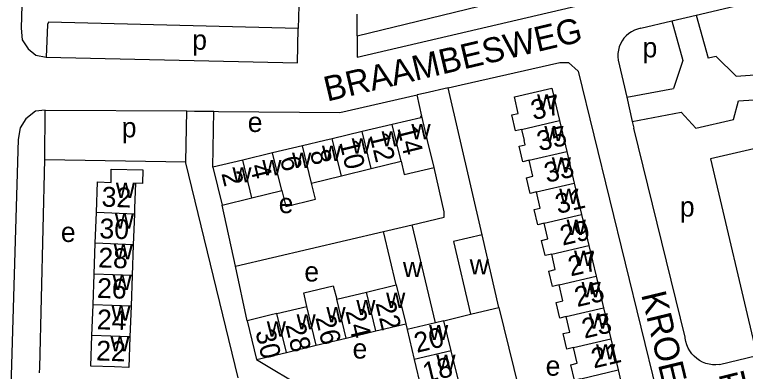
# Model space of a CAD drawing. Extents: x 161936 to 163647, y 386450 to 388633.
# Drawn here: x 162905.7 to 163052.8, y 387703.5 to 387775.4 of the extents above; entities that cross this region are included whole.
import ezdxf

# ---------------------------------------------------------------- set-up
doc = ezdxf.new("R2010")
doc.units = 0
for name, color, linetype in [('BLT_Basislijn', 7, 'Continuous'), ('BLT_Bebouwing', 7, 'Continuous'), ('BLT_Centroide', 7, 'Continuous'), ('BLT_Huisnummer', 7, 'Continuous'), ('BLT_Huisnummer_ tussenligend', 7, 'Continuous'), ('BLT_Onderverdeling_panden', 7, 'Continuous'), ('BLT_Straatnaam', 7, 'Continuous')]:
    doc.layers.add(name, color=color, linetype=linetype)

msp = doc.modelspace()

# ---------------------------------------------------------------- linework, layer by layer
at = {"layer": 'BLT_Basislijn'}
for p, q in [((163042.83, 387775.25), (163135.83, 387797.38)), ((162974.6, 387771.09), (163056.45, 387791.04)), ((162962.89, 387777.14), (162962.72, 387772.56)), ((162974.6, 387771.09), (162974.61, 387775.46)), ((163037.96, 387774.1), (163042.83, 387775.25)), ((163042.83, 387775.25), (163045.25, 387766.59)), ((163031.7, 387772.61), (163037.96, 387774.1)), ((163037.96, 387774.1), (163040.19, 387766.11)), ((163027.15, 387766.18), (163028.87, 387758.74)), ((163040.19, 387766.11), (163038.28, 387760.49)), ((162999.76, 387731.03), (162992.94, 387760.63)), ((163028.87, 387758.74), (163038.28, 387760.49)), ((162987.66, 387754.89), (162986.68, 387759.19)), ((163028.87, 387758.74), (163029.99, 387753.86)), ((162911.78, 387746.16), (162911.85, 387756.12)), ((162911.85, 387756.12), (162940.32, 387755.95)), ((162940.13, 387745.73), (162940.32, 387755.95)), ((162945.57, 387744.63), (162945.79, 387755.88)), ((163029.99, 387753.86), (163039.8, 387755.68)), ((163029.99, 387753.86), (163030.3, 387752.52)), ((163040.64, 387710.4), (163030.3, 387752.52)), ((162911.78, 387746.16), (162940.13, 387745.73)), ((162950.1, 387724.67), (162947.44, 387737.01)), ((162950.1, 387724.67), (162979.91, 387731.65)), ((162952.47, 387713.71), (162950.1, 387724.67)), ((163003.16, 387716.38), (163011.93, 387680.2)), ((162992.08, 387713.71), (162997.43, 387715.04)), ((162954.35, 387705.88), (162966.71, 387698.54)), ((163047.53, 387704.91), (163055.08, 387706.71))]:
    msp.add_line(p, q, dxfattribs=at)
for points in [[(162915.89, 387918.97), (162915.01, 387918.97), (162913.37, 387918.42), (162912.22, 387917.52), (162911.2, 387915.93), (162911.09, 387914.53), (162906.98, 387772.65), (162907.22, 387770.28), (162908.42, 387768.43), (162909.94, 387767.19), (162912.05, 387766.8)], [(162974.6, 387771.09), (162974.59, 387766.81), (163051.97, 387784.91), (163053.26, 387785.27), (163056.22, 387788.49), (163056.45, 387791.04)], [(162962.72, 387772.56), (162912.49, 387773.8), (162912.26, 387773.37), (162912.05, 387766.8)], [(162912.05, 387766.8), (162962.59, 387765.65), (162962.72, 387772.56)], [(163031.7, 387772.61), (163031.05, 387772.45), (163030.42, 387772.22), (163029.83, 387771.91), (163029.27, 387771.53), (163028.77, 387771.09), (163028.32, 387770.6), (163027.93, 387770.05), (163027.61, 387769.46), (163027.36, 387768.84), (163027.19, 387768.19), (163027.1, 387767.53), (163027.09, 387766.86), (163027.15, 387766.18)], [(163050.87, 387762.96), (163046.85, 387766.9), (163045.25, 387766.59)], [(162992.94, 387760.63), (162995.56, 387761.23), (163015.41, 387765.73), (163017.12, 387765.68), (163019.13, 387763.98), (163038.02, 387686.62), (163038.08, 387686.35)], [(163050.87, 387762.96), (163060.21, 387763.61), (163071.43, 387754.4)], [(162992.94, 387760.63), (162988.31, 387759.56), (162986.68, 387759.19)], [(162945.79, 387755.88), (162946.68, 387755.87), (162971.15, 387755.62), (162986.68, 387759.19)], [(163039.8, 387755.68), (163042.78, 387752.51), (163050.39, 387754.23), (163051.4, 387757.99)], [(163051.4, 387757.99), (163058.57, 387758.49), (163067.14, 387751.45)], [(162911.85, 387756.12), (162909.89, 387755.9), (162907.95, 387754.34), (162906.79, 387752.55), (162906.35, 387750.21), (162903.24, 387643.73), (162900.86, 387641.66), (162900.54, 387640.21), (162900.7, 387625.17), (162903.24, 387620), (162914.45, 387609.13)], [(162940.32, 387755.95), (162941.88, 387755.94), (162945.79, 387755.88)], [(163055.32, 387748.56), (163045.72, 387746.32), (163055.08, 387706.71)], [(162910.69, 387703.24), (162910.72, 387704.27), (162911.78, 387746.16)], [(162950.67, 387702.21), (162940.12, 387745.51), (162940.13, 387745.73)], [(162985.66, 387733.03), (162992.13, 387734.59), (162992.13, 387735.62), (162990.1, 387744.58)], [(163047.53, 387704.91), (163046.84, 387704.85), (163046.15, 387704.86), (163045.46, 387704.96), (163044.79, 387705.13), (163044.14, 387705.38), (163043.53, 387705.7), (163042.96, 387706.09), (163042.43, 387706.55), (163041.97, 387707.06), (163041.56, 387707.62), (163041.22, 387708.22), (163040.96, 387708.86), (163040.77, 387709.53), (163040.65, 387710.21), (163040.64, 387710.4)]]:
    msp.add_lwpolyline(points, dxfattribs=at)
at = {"layer": 'BLT_Bebouwing'}
for p, q in [((163013.79, 387760.55), (163015.32, 387754.04)), ((162981.63, 387753.22), (162975.62, 387751.79)), ((163015.32, 387754.04), (163016.79, 387747.8)), ((162975.62, 387751.79), (162969.61, 387750.36)), ((163007.72, 387752.25), (163008.25, 387750)), ((162963.6, 387748.93), (162957.59, 387747.49)), ((162957.59, 387747.49), (162951.58, 387746.06)), ((163016.79, 387747.8), (163018.29, 387741.42)), ((162951.58, 387746.06), (162945.57, 387744.63)), ((162977.44, 387744.36), (162983.44, 387745.83)), ((162945.57, 387744.63), (162947.44, 387737.01)), ((162971.44, 387742.89), (162977.44, 387744.36)), ((162965.44, 387741.42), (162971.44, 387742.89)), ((163018.29, 387741.42), (163019.78, 387735.1)), ((162953.44, 387738.48), (162959.44, 387739.95)), ((162947.44, 387737.01), (162953.44, 387738.48)), ((162921.89, 387729.3), (162922.12, 387735.48)), ((162929.78, 387735.2), (162929.56, 387729.02)), ((163019.78, 387735.1), (163021.24, 387728.89)), ((162990.4, 387713.31), (162985.66, 387733.03)), ((162982.49, 387720.91), (162979.91, 387731.65)), ((163003.16, 387716.38), (162999.76, 387731.03)), ((162921.67, 387723.12), (162921.89, 387729.3)), ((162929.56, 387729.02), (162929.33, 387722.85)), ((163021.24, 387728.89), (163022.71, 387722.66)), ((162921.45, 387716.94), (162921.67, 387723.12)), ((162929.33, 387722.85), (162929.11, 387716.67)), ((163022.71, 387722.66), (163024.2, 387716.31)), ((162976.5, 387719.48), (162982.49, 387720.91)), ((162970.49, 387718.03), (162976.5, 387719.48)), ((162921.22, 387710.77), (162921.45, 387716.94)), ((162929.11, 387716.67), (162928.88, 387710.49)), ((162958.48, 387715.15), (162964.49, 387716.59)), ((163000, 387715.64), (163003.16, 387716.38)), ((163024.2, 387716.31), (163025.68, 387710.05)), ((162997.43, 387715.04), (163000, 387715.64)), ((162952.47, 387713.71), (162954.35, 387705.88)), ((162978.38, 387711.65), (162984.38, 387713.1)), ((162984.38, 387713.1), (162984.65, 387711.98)), ((162992.08, 387713.71), (162990.4, 387713.31)), ((162993.53, 387707.68), (162992.08, 387713.71)), ((162972.37, 387710.21), (162978.38, 387711.65)), ((162984.65, 387711.98), (162986.11, 387705.9)), ((162966.36, 387708.77), (162972.37, 387710.21)), ((162960.36, 387707.33), (162966.36, 387708.77)), ((163025.68, 387710.05), (163027.15, 387703.8)), ((162954.35, 387705.88), (162960.36, 387707.33)), ((162994.98, 387701.65), (162993.53, 387707.68)), ((162986.11, 387705.9), (162987.56, 387699.87)), ((163027.15, 387703.8), (163028.63, 387697.51))]:
    msp.add_line(p, q, dxfattribs=at)
for points in [[(163007.72, 387752.25), (163006.47, 387751.96), (163005.72, 387755.16), (163007.04, 387755.47), (163006.26, 387758.78), (163013.79, 387760.55)], [(162987.66, 387754.89), (162987.36, 387754.82), (162987.42, 387754.6), (162981.63, 387753.22)], [(162990.1, 387744.58), (162988.8, 387750), (162987.66, 387754.89)], [(162969.61, 387750.36), (162968.11, 387750), (162963.6, 387748.93)], [(163009.22, 387746.02), (163007.97, 387745.73), (163007.24, 387748.84), (163008.45, 387749.12), (163008.25, 387750)], [(162983.44, 387745.83), (162984.1, 387743.15), (162990.1, 387744.58)], [(163010.71, 387739.64), (163009.45, 387739.34), (163008.7, 387742.52), (163009.98, 387742.82), (163009.22, 387746.02)], [(162922.12, 387735.48), (162922.34, 387741.66), (162925.08, 387741.56), (162925.13, 387744.23), (162931.48, 387744.11), (162931.38, 387741.33), (162930, 387741.38), (162929.82, 387736.38), (162929.78, 387735.2)], [(162959.44, 387739.95), (162960.29, 387736.71), (162966.25, 387738.16), (162965.44, 387741.42)], [(163012.25, 387733.33), (163010.97, 387733.03), (163010.25, 387736.11), (163011.47, 387736.39), (163010.71, 387739.64)], [(162979.91, 387731.65), (162980.8, 387731.87), (162985.66, 387733.03)], [(163013.77, 387727.13), (163012.43, 387726.82), (163011.71, 387729.89), (163012.99, 387730.19), (163012.25, 387733.33)], [(162999.76, 387731.03), (162994.02, 387729.69), (162997.43, 387715.04)], [(163015.25, 387720.91), (163013.92, 387720.59), (163013.19, 387723.69), (163014.5, 387724), (163013.77, 387727.13)], [(162964.49, 387716.59), (162963.86, 387719.3), (162969.81, 387720.73), (162970.49, 387718.03)], [(163016.66, 387714.54), (163015.38, 387714.24), (163014.64, 387717.39), (163016, 387717.71), (163015.25, 387720.91)], [(162958.48, 387715.15), (162957.33, 387714.87), (162952.47, 387713.71)], [(163018.16, 387708.29), (163016.81, 387707.97), (163016.06, 387711.11), (163017.4, 387711.43), (163016.66, 387714.54)], [(162928.88, 387710.49), (162928.66, 387704.31), (162925.75, 387704.41), (162921, 387704.59), (162921.22, 387710.77)], [(163019.62, 387702.03), (163018.33, 387701.73), (163017.6, 387704.84), (163018.9, 387705.14), (163018.16, 387708.29)]]:
    msp.add_lwpolyline(points, dxfattribs=at)
at = {"layer": 'BLT_Onderverdeling_panden'}
for p, q in [((162983.44, 387745.83), (162981.63, 387753.22)), ((163007.72, 387752.25), (163015.32, 387754.04)), ((162977.44, 387744.36), (162975.62, 387751.79)), ((162971.44, 387742.89), (162969.61, 387750.36)), ((162965.44, 387741.42), (162963.6, 387748.93)), ((162959.44, 387739.95), (162957.59, 387747.49)), ((163009.22, 387746.02), (163016.79, 387747.8)), ((162953.44, 387738.48), (162951.58, 387746.06)), ((163010.71, 387739.64), (163018.29, 387741.42)), ((162929.78, 387735.2), (162922.12, 387735.48)), ((163012.25, 387733.33), (163019.78, 387735.1)), ((162929.56, 387729.02), (162921.89, 387729.3)), ((163013.77, 387727.13), (163021.24, 387728.89)), ((162929.33, 387722.85), (162921.67, 387723.12)), ((163015.25, 387720.91), (163022.71, 387722.66)), ((162982.49, 387720.91), (162984.38, 387713.1)), ((162978.38, 387711.65), (162976.5, 387719.48)), ((162972.37, 387710.21), (162970.49, 387718.03)), ((162929.11, 387716.67), (162921.45, 387716.94)), ((162966.36, 387708.77), (162964.49, 387716.59)), ((163016.66, 387714.54), (163024.2, 387716.31)), ((162960.36, 387707.33), (162958.48, 387715.15)), ((162990.4, 387713.31), (162984.65, 387711.98)), ((162928.88, 387710.49), (162921.22, 387710.77)), ((163018.16, 387708.29), (163025.68, 387710.05)), ((162993.53, 387707.68), (162986.11, 387705.9)), ((163019.62, 387702.03), (163027.15, 387703.8))]:
    msp.add_line(p, q, dxfattribs=at)

# ---------------------------------------------------------------- texts
at = {"layer": 'BLT_Centroide'}
for s, p in [('p', (162941.42, 387768.28)), ('p', (163032.05, 387766.74)), ('w', (163010.83, 387756.25)), ('e', (162952.59, 387751.72)), ('p', (162927.23, 387750.64)), ('w', (162985.53, 387750.25)), ('w', (163012.29, 387749.88)), ('w', (162979.53, 387748.8)), ('w', (162973.52, 387747.34)), ('w', (162967.52, 387745.91)), ('w', (162961.52, 387744.45)), ('w', (162955.52, 387743)), ('w', (163013.79, 387743.56)), ('w', (162949.5, 387741.55)), ('w', (162926.05, 387738.44)), ('w', (163015.28, 387737.22)), ('e', (162958.82, 387735.38)), ('p', (163039.57, 387734.69)), ('w', (162925.84, 387732.25)), ('w', (163016.78, 387730.97)), ('e', (162914.98, 387729.57)), ('w', (162925.62, 387726.06)), ('w', (163018.27, 387724.75)), ('w', (162983.82, 387722.5)), ('w', (162997.26, 387723.03)), ('e', (162963.98, 387721.61)), ('w', (162925.38, 387719.91)), ('w', (163019.77, 387718.44)), ('w', (162980.44, 387716.28)), ('w', (162974.44, 387714.84)), ('w', (162925.16, 387713.72)), ('w', (162968.42, 387713.39)), ('w', (162962.42, 387711.95)), ('w', (163021.21, 387712.12)), ('w', (162956.42, 387710.52)), ('w', (162989.09, 387709.81)), ('w', (162924.95, 387707.53)), ('e', (162973.69, 387706.09)), ('w', (163022.69, 387705.91)), ('w', (162990.55, 387703.78)), ('e', (163012.55, 387702.64))]:
    msp.add_text(s, height=4, dxfattribs=at).set_placement(p)
at = {"layer": 'BLT_Huisnummer'}
for s, rotation, p in [('37', 13.243, (163010.1, 387754.08)), ('14', 283.7533, (162982.66, 387752.55)), ('10', 283.7543, (162971, 387749.67)), ('6', 283.7535, (162959.04, 387746.4)), ('2', 283.7544, (162947.26, 387743.38)), ('32', 357.9218, (162923.13, 387736.71)), ('31', 13.2418, (163015.02, 387735.19)), ('27', 13.2414, (163017.58, 387722.62)), ('26', 357.9218, (162922.2, 387718.34)), ('22', 283.504, (162978.28, 387717.26)), ('26', 283.504, (162966.19, 387714.35)), ('23', 13.2418, (163020.36, 387710.09)), ('30', 283.5024, (162954.1, 387711.51)), ('20', 13.5027, (162986.62, 387707.23)), ('22', 357.9279, (162922.02, 387705.73))]:
    msp.add_text(s, height=4, rotation=rotation, dxfattribs=at).set_placement(p)
at = {"layer": 'BLT_Huisnummer_ tussenligend'}
for s, rotation, p in [('35', 13.2418, (163011.32, 387747.82)), ('12', 283.7543, (162977.04, 387751.13)), ('8', 283.7535, (162965.08, 387747.69)), ('33', 13.2418, (163012.79, 387741.46)), ('4', 283.7544, (162952.97, 387744.86)), ('30', 357.9218, (162922.69, 387730.33)), ('29', 13.2414, (163015.96, 387728.82)), ('28', 357.9218, (162922.45, 387724.46)), ('25', 13.2418, (163018.89, 387716.45)), ('24', 357.9279, (162922.17, 387712.01)), ('24', 283.504, (162972.24, 387715.65)), ('28', 283.504, (162960.15, 387712.87)), ('21', 13.2426, (163022.25, 387704.09)), ('18', 13.5062, (162988.35, 387701.24))]:
    msp.add_text(s, height=4, rotation=rotation, dxfattribs=at).set_placement(p)
at = {"layer": 'BLT_Straatnaam'}
for s, height, rotation, p in [('BRAAMBESWEG', 4.9999, 13.2817, (162968.58, 387757.83)), ('KROEZELSTRAAT', 5, 283.5127, (163031.75, 387719.01)), ('TURFVELDENSTRAAT', 5, 13.7551, (163048.49, 387697.55))]:
    msp.add_text(s, height=height, rotation=rotation, dxfattribs=at).set_placement(p)

doc.saveas('drawing.dxf')
